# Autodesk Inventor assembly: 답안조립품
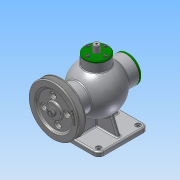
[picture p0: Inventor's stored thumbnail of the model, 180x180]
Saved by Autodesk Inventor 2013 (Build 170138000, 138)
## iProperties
Created: 2018-06
Part Number: 답안조립품
Document SubType Name: Assembly
Designer: Administrator
Author: Administrator
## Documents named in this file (19)
- C:\Users\Administrator\Desktop\480612V1012\답안조립품.iam
- C:\Users\Administrator\Desktop\480612V1012\본체.ipt
- C:\Users\Administrator\Desktop\480612V1012\V-벨트풀리.ipt
- C:\Users\Administrator\Desktop\480612V1012\너트 M8.ipt
- C:\Users\Administrator\Desktop\480612V1012\뒤커버.ipt
- C:\Users\Administrator\Desktop\480612V1012\멈춤링 15x1.ipt
- C:\Users\Administrator\Desktop\480612V1012\멈춤링 35x1.6.ipt
- 멈춤링 35x1.6.ipt
- C:\Users\Administrator\Desktop\480612V1012\베어링 6202.ipt
- 베어링 6202.ipt
- C:\Users\Administrator\Desktop\480612V1012\볼트 M4x12.ipt
- C:\Users\Administrator\Desktop\480612V1012\볼트 M4x16.ipt
- C:\Users\Administrator\Desktop\480612V1012\부시.ipt
- C:\Users\Administrator\Desktop\480612V1012\상부커버.ipt
- C:\Users\Administrator\Desktop\480612V1012\슬라이드.ipt
- C:\Users\Administrator\Desktop\480612V1012\앞커버.ipt
- C:\Users\Administrator\Desktop\480612V1012\오일 실 15 30 7.ipt
- C:\Users\Administrator\Desktop\480612V1012\키 4x4x12.ipt
- C:\Users\Administrator\Desktop\480612V1012\편심축.ipt
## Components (1 placed, 1 different names)
1. V-벨트풀리:1
